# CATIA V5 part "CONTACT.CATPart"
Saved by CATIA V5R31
Part number: CONTACT
Revision: 01
Nomenclature: CONTACT
Source: Unknown
Property "部品番号(B社)": "PLATE111111"
Property "部品名称(B社)": "CONTACT"
Property "Version(B社)": "01"
Property "材質(B社)": "C5210-1/2R"
Property "板厚": "0.15"
Bounding box of the stored display mesh (mm): x -4.1 to 4.5, y -3 to 9.257, z 0 to 2.017
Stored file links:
  \\solize.local\damia\dept\DDE_Design\10_order\2305701_JAMA_変換検証STEP3_お手本モデル作成\work\03_東洋電装_スイッチ\10_CATIA_V5\CONTACT.CATPart
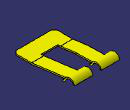
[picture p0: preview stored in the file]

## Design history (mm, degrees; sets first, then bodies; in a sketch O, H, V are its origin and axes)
WSupportSet1: ActiveGrid {3dwsupport RefPoint {point stored without definition}, 3DWOS ({wsupport Support xy-plane, RefPoint {3dwsupport}, GridIn {cartgrid Value 100, Stepbid1 0, Value 100, Stepbid2 0, Direction (1, 0, 0)}, GeometricData ({line type PtDir, Direction (1, 0, 0), Support xy-plane}; {line type PtDir, Direction (0, 1, 0), Support xy-plane})}; {wsupport Support yz-plane, RefPoint {3dwsupport}, GridIn {cartgrid Value 100, Stepbid1 0, Value 100, Stepbid2 0, Direction (0, 1, 0)}, GeometricData ({line type PtDir, Direction (0, 1, 0), Support yz-plane}; {line type PtDir, Direction (0, 0, 1), Support yz-plane})}; {wsupport Support zx-plane, RefPoint {3dwsupport}, GridIn {cartgrid Value 100, Stepbid1 0, Value 100, Stepbid2 0, Direction (0, 0, 1)}, GeometricData ({line type PtDir, Direction (0, 0, 1), Support zx-plane}; {line type PtDir, Direction (1, 0, 0), Support zx-plane})}), GeometricData ({line type PtDir, RefPoint {point stored without definition}, Direction (1, 0, 0), Support xy-plane}; {line type PtDir, RefPoint {point stored without definition}, Direction (0, 1, 0), Support xy-plane}; {line type PtDir, RefPoint {point stored without definition}, Direction (0, 1, 0), Support yz-plane}; {line type PtDir, RefPoint {point stored without definition}, Direction (0, 0, 1), Support yz-plane}; {line type PtDir, RefPoint {point stored without definition}, Direction (0, 0, 1), Support zx-plane}; {line type PtDir, RefPoint {point stored without definition}, Direction (1, 0, 0), Support zx-plane})}
Body1 (main body)
  Solid1 "PartBody": solid without history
